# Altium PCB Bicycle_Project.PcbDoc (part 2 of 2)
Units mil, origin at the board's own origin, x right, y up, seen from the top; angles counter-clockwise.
Board outline 2480.32 x 3188.98 mil, 2 copper layers (Top Layer, Bottom Layer), stack 35.085 mil thick; 108 components, 96 nets, 359 pads, 129 vias.
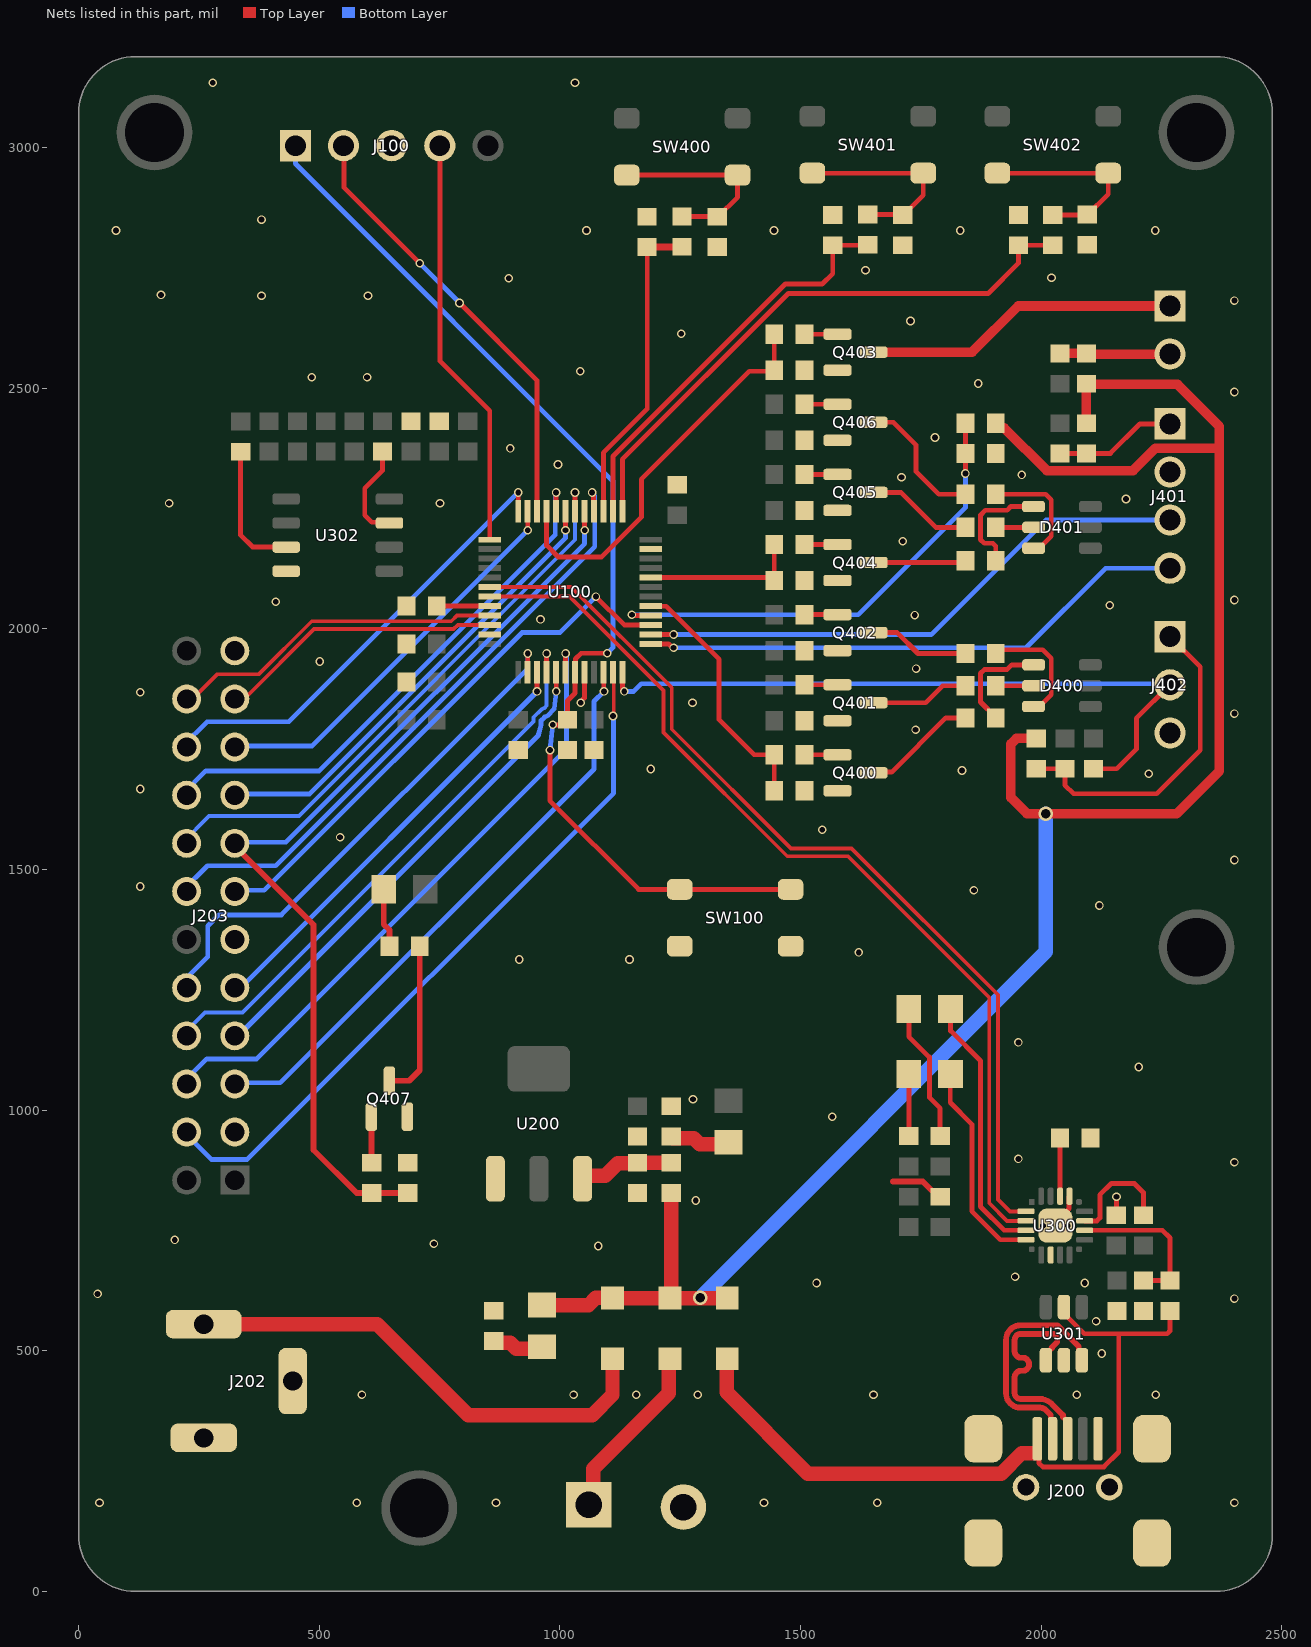
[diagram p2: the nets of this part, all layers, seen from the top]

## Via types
v1: diameter 18, hole 12, Top Layer to Bottom Layer, tented both sides, 127 vias
v2: diameter 30, hole 20, Top Layer to Bottom Layer, tented both sides, 2 vias

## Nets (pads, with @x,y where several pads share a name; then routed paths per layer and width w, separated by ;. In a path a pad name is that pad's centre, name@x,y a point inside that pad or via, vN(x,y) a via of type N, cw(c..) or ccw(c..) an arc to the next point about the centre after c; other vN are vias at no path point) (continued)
GND: C100.2 C101.2 C102.2 C103.2 C104.2 C105.2 C210.2 C211.2 C300.2 C301.2 C302.2 C303.2 C304.2 C400.1 C401.1 C402.1 J100.3 J200.0 J200.5 J201.2 J202.2 J202.3 J203.03 J203.11 J203.23 J401.2 J402.3 Q400.2 Q401.2 Q402.2 Q403.2 Q404.2 Q405.2 Q406.2 Q407.2 R100.2 R102.1 R200.1 R201.1 R301.2 R305.1 R406.1 R407.1 R408.1 R410.1 R417.1 R418.1 R419.1 R423.1 R424.1 R425.1 R429.1 SW100.2 U100.8 U100.23 U100.47 U200.1 U300.3 U300.12 U300.21 U301.2 U302.4 | length 288.9
  Top Layer w10: v1(1043.31,1846.46) 1043.31,1848.62 1051.06,1856.38 U100.8@1051.06,1909.72 ; U300.21@2029.45,760 2029.45,766.88 2058.07,795.5 2058.07,820.12 U300.12@2058.98,821.02 ; C302.2@2156.2,781.66 2156.5,781.95 v1(2156.5,819.88)
  Top Layer w12: 1692.31,851.38 1754.18,851.38 1773.18,832.38 1777.58,832.38 C300.2@1790.08,819.88
  other v1: 43.31,184.06 577.76,184.06 867.13,184.06 1424.21,184.06 1659.45,184.06 2401.57,184.06 588.58,408.46 1028.54,408.46 1158.46,408.46 1286.42,408.46 1651.57,408.46 2073.82,408.46 2238.19,408.46 2125.98,494.09 2114.17,561.02 2401.57,608.27 39.37,618.11 1533.46,640.75 2090.55,640.75 1945.87,653.54 1079.72,717.52 738.19,722.44 199.8,730.32 2003.94,759.84 2055.12,759.84 1282.48,812.01 2401.57,891.73 1952.76,898.62 1565.94,986.22 1276.57,1022.64 2202.76,1089.57 1952.76,1140.75 915.35,1312.99 1144.68,1312.99 1621.06,1327.76 2121.06,1425.2 1860.24,1456.69 127.95,1464.57 2401.57,1519.68 543.31,1566.93 1545.28,1582.68 127.95,1667.32 2223.43,1698.82 1835.63,1705.71 1188.98,1708.66 1739.17,1790.35 2401.57,1823.82 1275.59,1846.46 127.95,1868.11 1740.16,1917.32 500.98,1932.09 959.65,2019.61 1737.2,2028.54 2142.72,2049.21 409.45,2056.1 2401.57,2060.04 1712.6,2182.09 187.99,2260.83 750.98,2260.83 2176.18,2269.68 1709.65,2314.96 1959.65,2319.88 996.06,2341.54 896.65,2375 1779.53,2397.64 2401.57,2492.13 1869.09,2509.84 484.25,2522.64 599.41,2522.64 1042.32,2535.43 1251.97,2613.19 1728.35,2639.76 2401.57,2682.09 379.92,2691.93 601.38,2691.93 171.26,2693.9 893.7,2728.35 2021.65,2729.33 1634.84,2745.08 77.76,2827.76 1055.12,2827.76 1444.88,2827.76 1831.69,2827.76 2237.2,2827.76 379.92,2850.39 278.54,3134.84 1031.5,3134.84
LOAD: R409.1 R410.2 U100.33 | length 835.6
  Top Layer w10: U100.33@972.32,2244.37 972.39,2244.3 972.39,2173.28 996.06,2149.61 1086.83,2149.61 1169.29,2232.07 1169.29,2311.02 1393.7,2535.43 1443.43,2535.43 R410.2@1445.39,2537.4 R409.1@1445.39,2612.2
MCU_RX: U100.43 U300.18 | length 1952.9
  Top Layer w8: U100.43@854.21,2067.2 1020.21,2067.2 1215.17,1872.24 1215.17,1784.83 1472.44,1527.56 1598.43,1527.56 1892.02,1233.97 1892.02,807.09 1929.26,769.84 U300.18@1968.43,769.84
MCU_TX: U100.42 U300.17 | length 1951.2
  Top Layer w8: U100.42@854.21,2086.89 1023.15,2086.89 1232.28,1877.76 1232.28,1791.34 1480.06,1543.56 1606.05,1543.56 1910.02,1239.59 1910.02,814.54 1935.03,789.53 U300.17@1968.43,789.53
NetC210_1: C210.1 FB200.2 U200.3 | length 199.3
  Top Layer w30: U200.3@1046.93,857.29 1051.54,861.89 1051.54,863.65 1093.96,863.65 1120.11,889.8 1160.35,889.8 C210.1@1161.3,890.75 FB200.2@1231.3,890.75
NetD201_2: D201.2 R200.2 | length 108.5
  Top Layer w30: R200.2@862.8,520.15 866.3,516.65 896.73,516.65 909.45,503.94 958.54,503.94 D201.2@962.8,508.19
NetD204_2: D204.2 R201.2 | length 127.2
  Top Layer w30: R201.2@1231.3,944.88 1234.8,941.38 1278.11,941.38 1290.35,929.13 1346.46,929.13 D204.2@1350.39,933.07
NetD300_1: D300.1 R302.1 | length 129.1
  Top Layer w10: R302.1@1725.08,945.88 D300.1@1725.08,1075
NetD300_2: D300.2 U300.20 | length 441.2
  Top Layer w10: D300.2@1811.69,1075 1811.02,1074.33 1811.02,1015.75 1856.02,970.76 1856.02,789.65 1915.2,730.47 U300.20@1968.43,730.47
NetD301_1: D301.1 R303.1 | length 291
  Top Layer w10: D301.1@1725.08,1210 1725.08,1152.87 1767.72,1110.24 1767.72,1026.3 1790.08,1003.94 R303.1@1790.08,945.88
NetD301_2: D301.2 U300.19 | length 551.3
  Top Layer w10: D301.2@1811.69,1210 1811.69,1164.69 1874.02,1102.36 1874.02,799.21 1922.88,750.35 1968.23,750.35 U300.19@1968.43,750.16
NetD400_1: D400.1 R400.2 | length 223
  Top Layer w10: R400.2@1905.52,1814.96 1905.52,1816.46 1874.01,1847.96 1874.01,1907.27 1882.56,1915.82 1929.4,1915.82 1938.78,1925.2 D400.1@1984.25,1925.2
NetD400_2: D400.2 R401.2 | length 78.7
  Top Layer w10: R401.2@1905.51,1881.89 D400.2@1984.25,1881.89
NetD400_3: D400.3 R402.2 | length 248.4
  Top Layer w10: R402.2@1905.52,1948.82 1913.39,1956.69 2003.11,1956.69 2020.87,1938.93 2020.87,1863.39 1996.06,1838.58 D400.3@1984.25,1838.58
NetD401_1: D401.1 R411.2 | length 235.8
  Top Layer w10: R411.2@1905.52,2141.73 1905.52,2172.05 1899.66,2177.91 1881.63,2177.91 1874.02,2185.52 1874.02,2236.29 1884.25,2246.53 1929.4,2246.53 1937.09,2254.21 D401.1@1984.25,2254.21
NetD401_2: D401.2 R412.2 | length 78.7
  Top Layer w10: R412.2@1905.52,2210.91 D401.2@1984.25,2210.91
NetD401_3: D401.3 R413.2 | length 242.6
  Top Layer w10: R413.2@1905.52,2279.53 2009.3,2279.53 2020.87,2267.95 2020.87,2192.41 1996.06,2167.6 D401.3@1984.25,2167.6
NetD402_2: D402.2 R427.2 | length 123
  Top Layer w12: D402.2@633.86,1458.66 633.86,1385.83 645.67,1374.02 R427.2@645.67,1340.55
NetFB400_2: FB400.2 FB401.2 J400.2 | length 220.6
  Top Layer w20: FB401.2@2039.02,2572.41 FB400.2@2094.02,2572.41 2095.52,2570.91 J400.2@2259.02,2570.91
NetFB402_2: FB402.2 FB404.2 J402.1 | length 681.5
  Top Layer w10: FB402.2@1989.96,1709.41 FB404.2@2049.49,1709.41 2049.49,1675.47 2067.48,1657.48 2240.16,1657.48 2330.71,1748.03 2330.71,1920.78 J402.1@2267.72,1983.77
NetFB403_2: FB403.2 FB405.2 J401.1 | length 245.5
  Top Layer w10: FB405.2@2039.02,2364.41 FB403.2@2094.02,2364.41 2143.93,2364.41 2205.43,2425.91 J401.1@2259.02,2425.91
NetJ400_1: J400.1 Q403.3 | length 647.2
  Top Layer w20: Q403.3@1651.57,2574.8 1856.3,2574.8 1952.4,2670.91 J400.1@2259.02,2670.91
NetQ400_1: Q400.1 R403.2 | length 70.8
  Top Layer w10: R403.2@1508.39,1738.19 1570.87,1738.19 1573.82,1741.14 Q400.1@1576.77,1738.19
NetQ400_3: Q400.3 R400.1 | length 238.2
  Top Layer w10: Q400.3@1651.57,1700.79 1653.12,1702.33 1689.12,1702.33 1801.75,1814.96 R400.1@1842.52,1814.96
NetQ401_1: Q401.1 R404.2 | length 68.4
  Top Layer w10: R404.2@1508.39,1883.86 Q401.1@1576.77,1883.86
NetQ401_3: Q401.3 R401.1 | length 205.6
  Top Layer w10: Q401.3@1651.57,1846.46 1759.84,1846.46 1795.28,1881.89 R401.1@1842.51,1881.89
NetQ402_1: Q402.1 R405.2 | length 69.2
  Top Layer w10: R405.2@1508.39,2029.53 1574.8,2029.53 1575.79,2030.51 Q402.1@1576.77,2029.53
NetQ402_3: Q402.3 R402.1 | length 208.9
  Top Layer w10: Q402.3@1651.57,1992.13 1700.79,1992.13 1744.09,1948.82 R402.1@1842.52,1948.82
NetQ403_1: Q403.1 R409.2 | length 72.6
  Top Layer w10: R409.2@1508.39,2612.2 1573.82,2612.2 1576.77,2609.25 Q403.1@1576.77,2612.2
NetQ404_1: Q404.1 R414.2 | length 68.5
  Top Layer w10: R414.2@1508.39,2175.39 1508.59,2175.2 Q404.1@1576.77,2175.2
NetQ404_3: Q404.3 R411.1 | length 192.6
  Top Layer w10: Q404.3@1651.57,2137.8 1838.58,2137.8 R411.1@1842.52,2141.73
NetQ405_1: Q405.1 R415.2 | length 68.4
  Top Layer w10: R415.2@1508.39,2320.77 1508.49,2320.87 Q405.1@1576.77,2320.87
NetQ405_3: Q405.3 R412.1 | length 221
  Top Layer w10: Q405.3@1651.57,2283.46 1708.66,2283.46 1781.22,2210.91 R412.1@1842.52,2210.91
NetQ406_1: Q406.1 R416.2 | length 68.4
  Top Layer w10: R416.2@1508.39,2466.54 Q406.1@1576.77,2466.54
NetQ406_3: Q406.3 R413.1 | length 285.2
  Top Layer w10: Q406.3@1651.57,2429.13 1692.91,2429.13 1740.16,2381.89 1740.16,2326.77 1787.4,2279.53 R413.1@1842.52,2279.53
NetQ407_1: Q407.1 R428.2 | length 95.9
  Top Layer w12: Q407.1@608.27,986.22 608.27,891.68 R428.2@609.19,890.75
NetQ407_3: Q407.3 R427.1 | length 329.8
  Top Layer w12: Q407.3@645.67,1061.02 687.01,1061.02 708.67,1082.68 R427.1@708.67,1340.55
NetR100_1: R100.1 U100.44 | length 110.2
  Top Layer w10: R100.1@744.1,2047.24 744.37,2047.52 U100.44@854.21,2047.52
NetR300_2: R300.2 R301.1 U300.8 | length 327.6
  Top Layer w10: U300.8@2090.47,750.16 2251.86,750.16 2267.72,734.3 R300.2@2267.72,645.67 R301.1@2212.6,645.67
NetR304_2: R304.2 U300.9 | length 237.2
  Top Layer w10: U300.9@2090.47,769.84 2115.98,769.84 2122.05,775.91 2122.05,823.82 2145.67,847.44 2193.9,847.44 2212.6,828.74 R304.2@2212.6,781.66
NetR305_2: R305.2 U300.13 | length 120.9
  Top Layer w10: U300.13@2039.29,821.02 R305.2@2039.29,941.93
NetR306_1: R306.1 U302.3 | length 278.1
  Top Layer w10: R306.1@336.61,2368.11 336.61,2194.88 361.22,2170.28 430.67,2170.28 U302.3@431.14,2169.8
NetR309_1: R309.1 U302.7 | length 205.4
  Top Layer w10: R309.1@631.5,2368.3 631.5,2329.33 594.49,2292.32 594.49,2236.22 609.25,2221.46 644.06,2221.46 U302.7@645.71,2219.8
NetR420_1: R420.1 R423.2 SW400.1 | length 408.5
  Top Layer w10: SW400.1@1138.78,2942.91 SW400.1@1369.09,2942.91 1369.09,2897.13 1328.27,2856.3 R423.2@1326.77,2856.3 1326.06,2857.01 R420.1@1253.94,2857.01
NetR421_1: R421.1 R424.2 SW401.1 | length 408.5
  Top Layer w10: SW401.1@1524.61,2946.85 SW401.1@1754.92,2946.85 1754.92,2901.06 1714.1,2860.24 R424.2@1712.6,2860.24 1711.89,2860.95 R421.1@1639.76,2860.95
NetR422_1: R422.1 R425.2 SW402.1 | length 407
  Top Layer w10: SW402.1@1909.09,2946.85 SW402.1@2139.41,2946.85 2139.41,2903.11 2097.25,2860.95 R425.2@2095.75,2860.95 2095.04,2860.24 R422.1@2024.25,2860.24
PA0: J203.05 U100.10 | length 1234.6
  Top Layer w10: U100.10@1090.43,1909.72 1091.09,1909.07 1091.09,1870.74 v1(1091.75,1870.08)
  Bottom Layer w10: J203.05@316.54,1056.69 418.9,1056.69 1070.87,1708.66 1070.87,1849.2 v1(1091.75,1870.08)
PA1: J203.04 U100.11 | length 1487.5
  Top Layer w8: U100.11@1110.12,1909.72 1111.75,1908.09 1111.75,1820.41 v1(1110.24,1818.9)
  Bottom Layer w10: J203.04@216.54,956.69 275.59,897.64 350.39,897.64 1111.55,1658.8 1111.55,1817.58 v1(1110.24,1818.9)
PA5: J203.13 U100.15 | length 1149.4
  Top Layer w10: v1(1074.8,2066.93) 1133.58,2008.15 U100.15@1188.86,2008.15
  Bottom Layer w10: J203.13@316.54,1456.69 385.83,1456.69 921.26,1992.13 1000,1992.13 v1(1074.8,2066.93)
PA9: J203.16 U100.30 | length 1212.8
  Top Layer w10: U100.30@1031.38,2244.37 U100.30@1031.38,2244.37 1031.44,2283.41 v1(1031.5,2283.46)
  Bottom Layer w8: J203.16@216.54,1556.69 270.95,1611.1 457.56,1611.1 1031.5,2185.04 v1(1031.5,2283.46)
PA10: J203.17 U100.31 | length 971.1
  Top Layer w10: v1(1011.5,2204.72) 1011.59,2204.82 1011.59,2244.27 U100.31@1011.69,2244.37
  Bottom Layer w10: J203.17@316.54,1656.69 479.53,1656.69 1011.5,2188.66 v1(1011.5,2204.72)
PA11: J203.18 U100.32 | length 1125.1
  Top Layer w10: U100.32@992.01,2244.37 992.07,2244.43 992.07,2283.41 v1(992.13,2283.46)
  Bottom Layer w10: J203.18@216.54,1656.69 264.57,1704.72 500,1704.72 990.5,2195.22 990.5,2276.18 990.6,2276.28 990.6,2281.93 v1(992.13,2283.46)
PB8: J203.22 U100.45 | length 701.7
  Top Layer w8: J203.22@224.41,1854.33 236.49,1854.33 287.67,1905.51 374.02,1905.51 484.25,2015.75 774.27,2015.75 786.36,2027.83 U100.45@854.21,2027.83
PB9: J203.21 U100.46 | length 600.4
  Top Layer w8: J203.21@316.54,1856.69 346.41,1856.69 489.22,1999.5 779.24,1999.5 787.88,2008.15 U100.46@854.21,2008.15
PB15: J203.14 U100.28 | length 1307.3
  Top Layer w10: v1(1066.93,2283.46) 1066.93,2281.3 1069.75,2278.48 1069.75,2245.37 U100.28@1070.75,2244.37
  Bottom Layer w10: J203.14@216.54,1456.69 267.72,1507.87 409.45,1507.87 1072.5,2170.92 1072.5,2276.18 1066.93,2281.74 v1(1066.93,2283.46)
PB_DOWN: C402.2 R422.2 U100.25 | length 1208.5
  Top Layer w10: U100.25@1129.8,2244.37 1129.8,2352.08 1474.57,2696.85 1889.76,2696.85 1952.76,2759.84 C402.2@1952.76,2797.24 R422.2@2024.25,2797.24
PB_MODE: C401.2 R421.2 U100.26 | length 860.2
  Top Layer w10: U100.26@1110.12,2244.37 1110.12,2358.15 1468.5,2716.54 1545.28,2716.54 1566.93,2738.19 C401.2@1566.93,2797.24 1639.05,2797.24 R421.2@1639.76,2797.95
PB_UP: C400.2 R420.2 U100.27 | length 660.1
  Top Layer w10: U100.27@1090.43,2244.37 1090.43,2366.02 1181.46,2457.05 C400.2@1181.46,2793.66
  Top Layer w15: C400.2@1181.1,2793.3 1181.46,2793.66 1253.58,2793.66 R420.2@1253.94,2794.01
PC13: J203.10 U100.2 | length 1104.2
  Top Layer w10: U100.2@932.95,1909.72 933.01,1909.78 933.01,1948.76 v1(933.07,1948.82)
  Bottom Layer w10: J203.10@216.54,1256.69 216.54,1266.39 268.38,1318.23 268.38,1382.55 291.34,1405.51 421.26,1405.51 933.07,1917.32 v1(933.07,1948.82)
PC14: J203.09 U100.3 | length 929.9
  Top Layer w10: v1(952.44,1870.08) 952.54,1870.18 952.54,1909.63 U100.3@952.64,1909.72
  Bottom Layer w10: J203.09@316.54,1256.69 339.37,1256.69 952.44,1869.76 v1(952.44,1870.08)
PC15: J203.08 U100.4 | length 1191.7
  Top Layer w10: U100.4@972.32,1909.72 972.38,1909.78 v1(972.44,1948.82) v1(972.44,1948.82)
  Bottom Layer w8: J203.08@216.54,1156.69 216.79,1156.62 216.79,1156.94 262.6,1202.76 340.55,1202.76 945.03,1807.24 945.03,1816.19 961.43,1832.6 961.52,1832.6 967.75,1835.54 972.44,1840.22 v1(972.44,1948.82)
PF0: J203.07 U100.5 | length 1041.5
  Top Layer w10: U100.5@992.01,1909.72 992.22,1909.51 992.22,1870.3 v1(992.44,1870.08)
  Bottom Layer w10: J203.07@316.54,1156.69 324.19,1164.35 341.49,1164.35 954.54,1777.4 961.03,1800.61 961.03,1809.57 968.06,1816.6 974.38,1819.54 988.44,1833.6 v1(992.44,1870.08)
PF1: J203.06 U100.6 | length 1322.9
  Top Layer w10: U100.6@1011.69,1909.72 1011.75,1909.78 v1(1011.81,1948.82) v1(1011.81,1948.82)
  Bottom Layer w10: J203.06@216.54,1056.69 266.14,1106.3 370.08,1106.3 1013.44,1749.66 1013.44,1941.53 1013.34,1941.63 1013.34,1947.29 v1(1011.81,1948.82)
PF6: J203.19 U100.35 | length 841.8
  Top Layer w10: U100.35@932.95,2244.37 933.01,2244.31 933.01,2204.78 v1(933.07,2204.72)
  Bottom Layer w10: J203.19@316.54,1756.69 485.04,1756.69 v1(933.07,2204.72)
PF7: J203.20 U100.36 | length 954.2
  Top Layer w10: U100.36@913.27,2244.37 U100.36@913.27,2244.37 913.33,2283.41 v1(913.39,2283.46)
  Bottom Layer w10: J203.20@216.54,1756.69 266.93,1807.09 437.01,1807.09 v1(913.39,2283.46)
POWER_INPUT_MEASURE: R101.1 R102.2 U100.16 | length 1000.4
  Top Layer w10: v1(1149.61,2029.15) 1150.92,2027.83 U100.16@1188.86,2027.83 ; v1(1842.52,2322.83) R102.2@1842.52,2364.41 R101.1@1842.52,2427.41
  Bottom Layer w10: v1(1149.61,2029.15) 1619.7,2029.15 1842.52,2251.97 v1(1842.52,2322.83)
R_SPEED_LED: R403.1 R406.2 U100.17 | length 533.3
  Top Layer w10: U100.17@1188.86,2047.52 1189.54,2046.83 1220.88,2046.83 1330.71,1937.01 1330.71,1811.02 1403.54,1738.19 R403.1@1445.39,1738.19 R406.2@1445.39,1663.39
R_TEMP_LED: R414.1 R417.2 U100.20 | length 334.1
  Top Layer w10: U100.20@1188.86,2106.57 1439.21,2106.57 R417.2@1445.39,2100.39 R414.1@1445.39,2175.39
RESET_MCU: C105.1 J100.1 SW100.1 U100.7 | length 2306.8
  Top Layer w10: v1(979.33,1748.02) 979.33,1642.72 1163.39,1458.66 SW100.1@1249.02,1458.66 SW100.1@1479.33,1458.66 ; v1(985.07,1800.52) 1005.25,1800.52 C105.1@1015.75,1811.02 1015.75,1850.4 1031.38,1866.03 U100.7@1031.38,1909.72 1032.38,1910.72 1032.38,1937.51 1044.09,1949.22 1098.33,1949.22 v1(1098.46,1949.1)
  Bottom Layer w10: J100.1@450.39,3003.94 450.39,2966.93 1110.24,2307.09 1110.24,1960.87 v1(1098.46,1949.1) ; v1(979.33,1748.02) v1(985.07,1800.52)
SETTING_LED: J203.15 R428.1 R429.2 U100.29 | length 2002.5
  Top Layer w10: U100.29@1051.06,2244.37 1051.28,2244.15 1051.28,2204.94 v1(1051.5,2204.72)
  Top Layer w12: J203.15@316.54,1556.69 488.19,1385.04 488.19,917.32 577.76,827.75 R428.1@609.19,827.75 R429.2@684,827.75
  Bottom Layer w10: J203.15@316.54,1556.69 430.71,1556.69 1051.18,2177.17 1051.18,2204.41 v1(1051.5,2204.72)
SPEED_SENSOR_ANALOG_PIN: J401.4 U100.13 | length 1150.6
  Top Layer w10: U100.13@1188.86,1968.78 1189.13,1968.5 1226.18,1968.5 1234.06,1960.63 v1(1236.22,1960.63)
  Bottom Layer w10: v1(1236.22,1960.63) 1968.5,1960.63 2133.86,2125.98 J401.4@2267.59,2126
SPEED_SENSOR_DIGITAL_PIN: J401.3 U100.14 | length 1181.8
  Top Layer w10: U100.14@1188.86,1988.46 1189,1988.33 1236.08,1988.33 v1(1236.22,1988.19)
  Bottom Layer w10: v1(1236.22,1988.19) 1771.65,1988.19 2009.46,2226 J401.3@2272,2226
SYS_SWCLK: J100.4 U100.37 | length 861.3
  Top Layer w10: J100.4@751.18,3003.94 751.18,2555.91 854.21,2452.87 U100.37@854.21,2185.32
SYS_SWDIO: J100.2 U100.34 | length 925.9
  Top Layer w10: J100.2@551.18,3003.94 551.18,2917.32 v1(708.66,2759.84) ; v1(791.34,2677.17) 952.64,2515.87 U100.34@952.64,2244.37
  Bottom Layer w10: v1(708.66,2759.84) v1(791.34,2677.17)
TEMPERATURE_SENSOR: J402.2 R426.2 U100.12 | length 1441.4
  Top Layer w10: U100.12@1129.8,1909.72 1130.19,1909.33 1130.19,1875.91 1133.86,1872.24 v1(1133.86,1870.08) ; R426.2@2109.02,1709.41 2157.24,1709.41 2197.83,1750 2197.83,1813.89 J402.2@2267.72,1883.77
  Bottom Layer w10: v1(1133.86,1870.08) 1153.54,1870.08 1169.37,1885.91 J402.2@2259.02,1885.91
USB_D_N: J200.2 U301.3 | length 495.2
  Top Layer w12: 2009.47,376.67 ccw(c1996.88,364.08) 1996.88,381.89 1956.85,381.89 cw(c1956.85,411.81) 1935.69,390.65 1935.63,390.72 cw(c1956.75,411.83) 1926.88,411.83 1926.88,521.99 cw(c1958.32,521.99) 1936.09,544.22 1936.15,544.28 cw(c1957.1,523.34) 1957.1,552.96 2033.74,552.96 2078.1,508.6 2078.1,486.86 U301.3@2084.65,480.32 ; 2009.47,376.67 2019.89,366.26 2019.89,320.66 J200.2@2023.62,316.93
USB_D_P: J200.3 U301.1 | length 476.2
  Top Layer w12: U301.1@2009.84,480.32 2009.84,493.33 2022.45,505.93 2022.45,507.13 2033.31,517.99 2033.31,527.93 2026.28,534.96 1957.18,534.96 ccw(c1957.18,523.13) 1948.82,531.5 ccw(c1958.32,521.99) 1944.88,521.99 1944.88,521.55 1944.88,498.89 ccw(c1958.38,498.89) 1958.38,485.39 1961.38,485.39 cw(c1961.38,471.89) 1961.38,458.39 1958.38,458.39 ccw(c1958.38,444.89) 1944.88,444.89 1944.88,411.89 ccw(c1956.88,411.89) 1948.4,403.4 ccw(c1956.88,411.89) 1956.88,399.89 1996.88,399.89 cw(c1996.88,364.08) 2022.18,389.42 2045.44,366.16 2045.46,362.02 2055.12,352.36 J200.3@2055.12,316.93
VIN: D200.1 D201.1 D202.1 D203.1 FB200.1 FB400.1 FB402.1 FB403.1 R101.2 | length 4186.3
  Top Layer w20: R101.2@1905.52,2427.41 1905.52,2425.91 1914.02,2417.41 1923.15,2417.41 2011.81,2328.74 2190.94,2328.74 2237.68,2375.48 2370,2375.48 ; FB402.1@1989.96,1772.41 1948.72,1772.41 1937.01,1760.69 1937.01,1649.61 1970.53,1616.09 v2(2009.9,1616.09) 2282.09,1616.09 2370,1704 2370,2375.48 ; FB403.1@2094.02,2427.41 2094.02,2506.34 2095.55,2507.87 2283.46,2507.87 2370,2421.34 2370,2375.48
  Top Layer w30: D201.1@962.8,594.8 1059.37,594.8 1074.8,610.24 1108.56,610.24 D200.1@1109.31,609.49 D203.1@1228.55,609.49 1290.59,609.49 v2(1291.34,610.24) 1292.09,609.49 D202.1@1347.8,609.49 ; D203.1@1231.3,615.9 FB200.1@1231.3,819.88
  Bottom Layer w30: v2(1291.34,610.24) 2009.9,1328.8 v2(2009.9,1616.09)
VIN_BORNER: D203.2 J201.1 | length 373.4
  Top Layer w30: J201.1@1059.79,180 1069.63,189.84 1069.63,254.67 1226.26,411.29 1226.26,481.21 D203.2@1228.55,483.5
VIN_POWER_JACK: D200.2 J202.1 | length 1020.3
  Top Layer w30: J202.1@259.84,555.12 620.45,555.12 809.43,366.14 1066.93,366.14 1109.31,408.52 D200.2@1109.31,483.5
VIN_USB: D202.2 J200.1 R300.1 U301.5 | length 1605.1
  Top Layer w10: J200.1@1996.97,286.66 1996.97,312.09 J200.1@1992.13,316.93 1992.13,312.09 1992.13,286.66 1995.23,283.56 1995.23,266.58 2003.16,258.65 2130.45,258.65 2161.42,289.62 2161.42,535.43 ; U301.5@2047.24,590.55 2047.24,577.76 2089.56,535.43 2161.42,535.43 ; R300.1@2267.72,582.67 2267.72,541.29 2261.86,535.43 2161.42,535.43
  Top Layer w30: D202.2@1347.8,483.5 1346.46,482.17 1346.46,413.39 1515.13,244.72 1917.29,244.72 1959.23,286.66 J200.1@1986.97,286.66
pads on no net: J200.4 U300.1 U300.2 U300.10 U300.11 U300.14 U300.15 U300.16

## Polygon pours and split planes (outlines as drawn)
GND on Bottom Layer "GND_L02_P012" (solid, pour order 12): 0,118.11 0,3070.87 cw(c118.11,3070.87) 118.11,3188.98 2362.2,3188.98 cw(c2362.2,3070.87) 2480.32,3070.87 2480.32,118.11 cw(c2362.2,118.11) 2362.2,0 118.11,0 cw(c118.11,118.11)
EP on Bottom Layer "EP_L02_P011" (solid, pour order 11): 744.09,1287.4 681.1,1224.41 681.1,854.33 748.03,787.4 1181.1,787.4 1244.09,850.39 1244.09,1232.28 1188.98,1287.4
GND on Top Layer "GND_TOP" (solid, remove dead copper, pour order 3): 0,118.11 0,3070.87 cw(c118.11,3070.87) 118.11,3188.98 2362.2,3188.98 cw(c2362.2,3070.87) 2480.32,3070.87 2480.32,118.11 cw(c2362.2,118.11) 2362.2,0 118.11,0 cw(c118.11,118.11)

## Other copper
Top Layer:
  pour cut-out: 1871.06,1246.06 1870.6,1246.53 1692.49,1246.53 1692.49,1038.47 1712.76,1038.47 1712.76,972.18 1712.84,972.09 1712.13,971.38 1698.08,971.38 1698.08,731.38 1817.08,731.38 1817.08,803.3 1884.84,871.06 1884.84,1241.14
  pour cut-out: 309.61,2405.61 309.61,2393.61 314.44,2388.78 326.77,2388.78 326.77,2411.42 313.24,2411.42
  pour cut-out: 1980.22,2638.33 1980.32,2638.43 1980.32,2653.54 1991.14,2653.54 1998.03,2660.43 2003.94,2654.53 2003.94,2630.91
  pour cut-out: 673.38,2251.74 673.38,2237.87 665.7,2236.22 653.54,2236.22 653.54,2252.95 651.57,2254.92
  pour cut-out: 1817.02,2114.73 1817.02,2306.53 1915.37,2306.53 1966.54,2148.53 1932,2148.53 1931.02,2147.55 1931.02,2114.73
  pour cut-out: 2012.02,2401.91 2012.02,2389.91 2016.59,2389.91 2021.65,2384.84 2024.61,2387.8 2024.61,2405.51
  pour cut-out: 261.85,1854.33 286.97,1854.33 291.99,1859.35 291.99,1873.05 265.33,1873.05 263.78,1865.16
  pour cut-out: 460.14,2202.48 458.82,2201.15 458.82,2187.87 454.78,2187.87 453.78,2188.87 453.78,2200.74
Bottom Layer:
  pour cut-out: 2272.79,2186.52 2272.79,2165.48 2264.79,2157.48 2253.94,2157.48 2222.44,2125.98 2133.86,2125.98 1968.5,1960.63 1746.06,1960.63 1746.06,1972.44 1997.05,2223.43 2239.17,2223.43 2257.87,2204.72
  pour cut-out: 1021.65,1830.71 1022.64,1831.69 1066.93,1831.69 1066.93,1712.6 1070.87,1708.66 424.21,1062.01 332.09,1062.01 324.41,1054.33 318.11,1060.63 318.11,1106.3 370.08,1106.3 1013.44,1749.66 1013.44,1830.37 1013.78,1830.71
  pour cut-out: 934.06,1852.36 944.88,1863.19 985.07,1863.19 985.07,1734.08 331.69,1080.71 331.69,1251.01
  pour cut-out: 275.59,1692.51 219.52,1692.51 224.41,1754.33 264.57,1786.61 253.94,1797.24 263.78,1807.09 437.01,1807.09 913.39,2283.46 992.13,2283.46 990.5,2281.83 990.5,2195.22 500,1704.72
  pour cut-out: 408.46,1512.8 382.87,1512.8 315.94,1445.87 315.94,1405.51 291.34,1405.51 268.38,1382.55 268.38,1317.59 230.32,1279.53 228.35,1281.5 228.35,1516.73 251.97,1540.35 405.51,1540.35
  pour cut-out: 228.35,1492.93 228.35,1668.5 264.57,1704.72 500,1704.72 500,1604.33 408.46,1512.8 244.97,1512.8
  pour cut-out: 1001.19,2287.4 1022.43,2287.4 1015.5,2280.46 1015.5,2277.02 1008.13,2277.02
  pour cut-out: 986.01,1957.88 998.25,1957.88 1001.21,1954.92 1001.21,1936.8 988.96,1936.8 986.01,1939.76

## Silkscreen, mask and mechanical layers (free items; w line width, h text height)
Top Overlay:
  lines w5: 1659.45,1657.48 1653.54,1663.39 ; 1659.45,1669.29 1653.54,1663.39 ; 1659.45,1805.12 1653.54,1811.02 ; 1659.45,1816.93 1653.54,1811.02 ; 1659.45,1952.76 1653.54,1958.66 ; 1659.45,1964.57 1653.54,1958.66 ; 1659.45,2100.39 1653.54,2106.3 ; 1659.45,2112.2 1653.54,2106.3 ; 1659.45,2238.19 1653.54,2244.09 ; 1659.45,2250 1653.54,2244.09 ; 1659.45,2385.83 1653.54,2391.73 ; 1659.45,2397.64 1653.54,2391.73 ; 1659.45,2529.53 1653.54,2535.43 ; 1659.45,2541.34 1653.54,2535.43 ; 1692.91,1633.86 1830.71,1633.86 1830.71,1334.65 1692.91,1334.65 1692.91,2535.43 1653.54,2535.43 ; 1692.91,1663.39 1653.54,1663.39 ; 1692.91,1811.02 1653.54,1811.02 ; 1692.91,1958.66 1653.54,1958.66 ; 1692.91,2106.3 1653.54,2106.3 ; 1692.91,2244.09 1653.54,2244.09 ; 1692.91,2391.73 1653.54,2391.73
  text "PROGRAMING PORT" at 435.33,3120.52 h30
  text "RST" at 470.59,2842.14 h30 r90
  text "GND" at 667.44,2842.14 h30 r90
  text "3V3" at 868.23,2842.14 h30 r90
  text "SWDIO" at 565.08,2787.15 h30 r90
  text "SWCLK" at 765.87,2782.16 h30 r90
  text "-" at 2355.39,2659.3 h30
  text "+" at 2356.38,2555.12 h30
  text "VCC" at 2347.52,2410.51 h30
  text "Guard" at 222.28,2356.46 h60 r90
  text "GND" at 2347.52,2312.09 h30
  text "DO" at 2347.52,2213.66 h30
  text "ThermoWheel" at 135.67,2195.04 h60 r90
  text "AO" at 2347.52,2115.24 h30
  text "I_SPEED" at 1947.28,2100.55 h30
  text "I_TEMP" at 1962.27,2006.06 h30
  text "VCC" at 2347.52,1969.57 h30
  text "3V3" at 74.22,1942.01 h30
  text "GND" at 386.89,1942.01 h30
  text "DQ" at 2347.52,1869.17 h30
  text "PB8" at 74.22,1841.88 h30
  text "PB9" at 386.89,1841.88 h30
  text "GND" at 2347.52,1768.78 h30
  text "SDA2" at 36.5,1745.16 h30
  text "SCL2" at 386.89,1741.76 h30
  text "PA11" at 52.47,1660.51 h30
  text "PA10" at 386.89,1641.63 h30
  text "~" at 86.69,1613.05 h30
  text "PA9" at 74.22,1541.51 h30
  text "PA8" at 386.89,1541.51 h30
  text "SETTING" at 579.7,1514.76 h30
  text "PA5" at 388.8,1445.32 h30
  text "PB15" at 49.23,1441.38 h30
  text "3V3" at 74.22,1341.26 h30
  text "GND" at 386.89,1341.26 h30
  text "PC13" at 398.7,1245.16 h30
  text "PC13" at 50.28,1242.2 h30
  text "MCU_TX" at 1863.27,1196.17 h30
  text "PC15" at 48.31,1142.8 h30
  text "PF0" at 394.76,1142.8 h30
  text "POWER" at 1277.1,1114.17 h30
  text "PA0" at 392.8,1070.94 h30
  text "3V3" at 1307.09,1070.87 h30
  text "MCU_RX" at 1863.27,1058.37 h30
  text "PF1" at 75.87,1040.43 h30
  text "A0" at 406.57,1030.59 h30
  text "PA1" at 73.9,952.83 h30
  text "GND" at 386.89,940.76 h30
  text "A1" at 92.6,910.51 h30
  text "3V3" at 74.22,840.63 h30
  text "3V3" at 386.89,840.63 h30
  text "POWER" at 890.65,686.1 h30
  text "VIN" at 923.14,642.8 h30
  text "+" at 1043.13,356 h50
  text "-" at 1239.98,356 h50
  text "JACK - 5V" at 61.93,183.53 h30 r90
  text "USB_PORT" at 1812.84,64.06 h30 r90
  text "BORNER - 5V" at 947.76,16.81 h30 r90
Bottom Overlay:
  drawing of 902 lines, arcs and shapes, not listed
  text "J400" at 825.71,2717.6 h30
  text "J100" at 1635.02,2709.72 h30
  text "(I/O=PA12)" at 829.65,2628.11 h30
  text "LOAD" at 971.38,2628.11 h30
  text "Programming Port" at 1809.96,2625.23 h30
  text "-" at 599.49,2542.17 h30
  text "3V3" at 1924.13,2540.43 h30
  text "+" at 827.83,2539.37 h30
  text "RST" at 1309.96,2536.5 h30
  text "SWDIO" at 1487.13,2536.5 h30
  text "GND" at 1609.17,2536.5 h30
  text "SWDLK" at 1798.15,2536.5 h30
  text "GND" at 652.48,2469.57 h30
  text "5V / 3V3" at 952.79,2469.57 h30
  text "NRST" at 1325.71,2465.63 h30
  text "PA13" at 1472.13,2465.63 h30
  text "GND" at 1613.11,2465.63 h30
  text "PA14" at 1780.66,2465.63 h30
  text "3V3" at 1928.07,2465.63 h30
  text "J402" at 825.71,2351.46 h30
  text "J401" at 1632.52,2347.52 h30
  text "Speed Encoder Module" at 1874.94,2266.97 h30
  text "Sensor DS18B20" at 983.19,2264.84 h30
  text "VCC" at 664.12,2178.23 h30
  text "DQ" at 865.83,2178.23 h30
  text "GND" at 1030.43,2178.23 h30
  text "VCC" at 1412.15,2177.24 h30
  text "GND" at 1633.78,2177.24 h30
  text "DO" at 1761.5,2177.24 h30
  text "A0" at 1900.28,2177.24 h30
  text "PA2" at 880.83,2107.36 h30
  text "GND" at 1030.43,2107.36 h30
  text "5V / 3V3" at 739.09,2103.43 h30
  text "5V / 3V3" at 1487.13,2103.43 h30
  text "GND" at 1633.78,2103.43 h30
  text "PA4" at 1776.5,2103.43 h30
  text "PA3" at 1915.28,2103.43 h30
  text "LEDs" at 1637.52,1961.12 h30
  text "PUSH BUTTONS" at 945.67,1957.76 h30
  text "Function" at 1105.24,1902.64 h30
  text "GPIO" at 1347.36,1902.07 h30
  text "Function" at 1989.09,1902.07 h30
  text "Designator" at 857.2,1900.82 h30
  text "Designator" at 1741.06,1900.25 h30
  text "GPIO" at 550.12,1898.7 h30
  text "PB2" at 1262.72,1835.71 h30
  text "PB14" at 550.12,1833.39 h30
  text "SW400" at 789.73,1833.39 h30
  text "RED" at 1412.1,1833.25 h30
  text "UP" at 1022.39,1829.45 h30
  text "I_TEMP" at 1961.6,1773.21 h30
  text "PB10" at 1275.21,1768.8 h30
  text "GREEN" at 1442.09,1768.8 h30
  text "D400" at 1658.59,1769.37 h30
  text "PB13" at 550.12,1766.32 h30
  text "SW401" at 784.73,1766.32 h30
  text "OK/MODE" at 1097.36,1764.84 h30
  text "PB11" at 1270.21,1704.35 h30
  text "BLUE" at 1427.1,1704.35 h30
  text "PB12" at 550.12,1703.33 h30
  text "SW402" at 789.73,1703.33 h30
  text "DOWN" at 1052.38,1699.39 h30
  text "PA7" at 1262.72,1640.33 h30
  text "RED" at 1412.1,1640.33 h30
  text "I_SPEED" at 1976.6,1584.23 h30
  text "D401" at 1653.59,1580.39 h30
  text "PB0" at 1262.72,1575.89 h30
  text "GREEN" at 1442.09,1575.89 h30
  text "PB1" at 1257.72,1511.44 h30
  text "BLUE" at 1427.1,1511.44 h30
  text "Edward  F. Goyeneche" at 85.86,1107.36 h30 r270
  text "Gustavo A. Pisso" at 40.43,1103.43 h30 r270
Board Shape:
  the board outline again, w10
